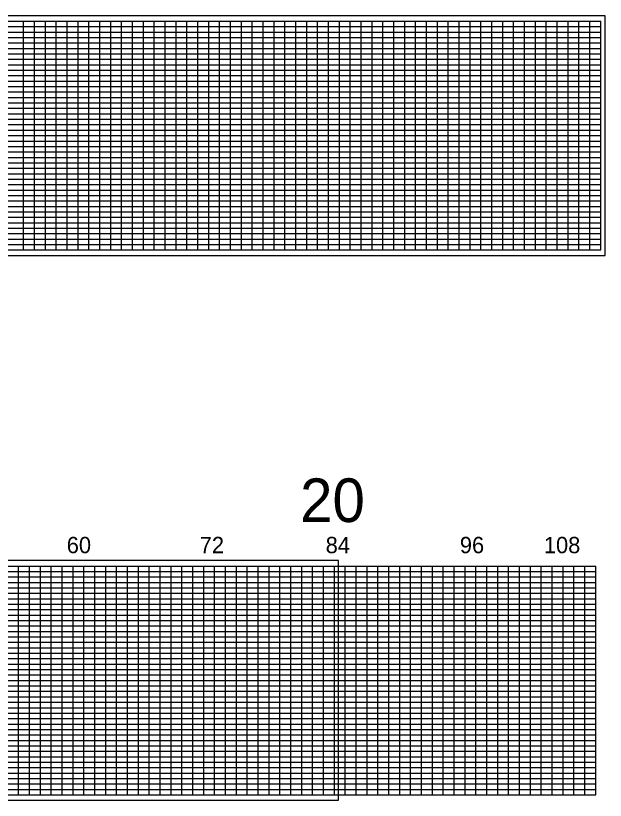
# Model space of a CAD drawing. Extents: x 1914168 to 1925341, y 720939 to 777401.
# Drawn here: x 1922518 to 1925226, y 735939 to 739539 of the extents above; entities that cross this region are included whole.
import ezdxf

# ---------------------------------------------------------------- set-up
doc = ezdxf.new("R2010")
doc.units = 0
for name, color, linetype in [('RD_PD_ALT1_CL', 7, 'Continuous'), ('RD_PD_WallFill', 7, 'Continuous'), ('RD_SHT_IplotShp', 7, 'Continuous')]:
    doc.layers.add(name, color=color, linetype=linetype)

msp = doc.modelspace()

# ---------------------------------------------------------------- linework, layer by layer
at = {"layer": 'RD_PD_WallFill'}
for p, q in [((1919854.9, 739514.2), (1925204.9, 739514.2)), ((1922554.9, 738464.2), (1922554.9, 739514.2)), ((1922554.9, 738464.2), (1922554.9, 739514.2)), ((1922604.9, 738464.2), (1922604.9, 739514.2)), ((1922604.9, 738464.2), (1922604.9, 739514.2)), ((1922654.9, 738464.2), (1922654.9, 739514.2)), ((1922654.9, 738464.2), (1922654.9, 739514.2)), ((1922704.9, 738464.2), (1922704.9, 739514.2)), ((1922704.9, 738464.2), (1922704.9, 739514.2)), ((1922754.9, 738464.2), (1922754.9, 739514.2)), ((1922754.9, 738464.2), (1922754.9, 739514.2)), ((1922804.9, 738464.2), (1922804.9, 739514.2)), ((1922804.9, 738464.2), (1922804.9, 739514.2)), ((1922854.9, 738464.2), (1922854.9, 739514.2)), ((1922854.9, 738464.2), (1922854.9, 739514.2)), ((1922904.9, 738464.2), (1922904.9, 739514.2)), ((1922904.9, 738464.2), (1922904.9, 739514.2)), ((1922954.9, 738464.2), (1922954.9, 739514.2)), ((1922954.9, 738464.2), (1922954.9, 739514.2)), ((1923004.9, 738464.2), (1923004.9, 739514.2)), ((1923004.9, 738464.2), (1923004.9, 739514.2)), ((1923054.9, 738464.2), (1923054.9, 739514.2)), ((1923054.9, 738464.2), (1923054.9, 739514.2)), ((1923104.9, 738464.2), (1923104.9, 739514.2)), ((1923104.9, 738464.2), (1923104.9, 739514.2)), ((1923154.9, 738464.2), (1923154.9, 739514.2)), ((1923154.9, 738464.2), (1923154.9, 739514.2)), ((1923204.9, 738464.2), (1923204.9, 739514.2)), ((1923204.9, 738464.2), (1923204.9, 739514.2)), ((1923254.9, 738464.2), (1923254.9, 739514.2)), ((1923254.9, 738464.2), (1923254.9, 739514.2)), ((1923304.9, 738464.2), (1923304.9, 739514.2)), ((1923304.9, 738464.2), (1923304.9, 739514.2)), ((1923354.9, 738464.2), (1923354.9, 739514.2)), ((1923354.9, 738464.2), (1923354.9, 739514.2)), ((1923404.9, 738464.2), (1923404.9, 739514.2)), ((1923404.9, 738464.2), (1923404.9, 739514.2)), ((1923454.9, 738464.2), (1923454.9, 739514.2)), ((1923454.9, 738464.2), (1923454.9, 739514.2)), ((1923504.9, 738464.2), (1923504.9, 739514.2)), ((1923504.9, 738464.2), (1923504.9, 739514.2)), ((1923554.9, 738464.2), (1923554.9, 739514.2)), ((1923554.9, 738464.2), (1923554.9, 739514.2)), ((1923604.9, 738464.2), (1923604.9, 739514.2)), ((1923604.9, 738464.2), (1923604.9, 739514.2)), ((1923654.9, 738464.2), (1923654.9, 739514.2)), ((1923654.9, 738464.2), (1923654.9, 739514.2)), ((1923704.9, 738464.2), (1923704.9, 739514.2)), ((1923704.9, 738464.2), (1923704.9, 739514.2)), ((1923754.9, 738464.2), (1923754.9, 739514.2)), ((1923754.9, 738464.2), (1923754.9, 739514.2)), ((1923804.9, 738464.2), (1923804.9, 739514.2)), ((1923804.9, 738464.2), (1923804.9, 739514.2)), ((1923854.9, 738464.2), (1923854.9, 739514.2)), ((1923854.9, 738464.2), (1923854.9, 739514.2)), ((1923904.9, 738464.2), (1923904.9, 739514.2)), ((1923904.9, 738464.2), (1923904.9, 739514.2)), ((1923954.9, 738464.2), (1923954.9, 739514.2)), ((1923954.9, 738464.2), (1923954.9, 739514.2)), ((1924004.9, 738464.2), (1924004.9, 739514.2)), ((1924004.9, 738464.2), (1924004.9, 739514.2)), ((1924054.9, 738464.2), (1924054.9, 739514.2)), ((1924054.9, 738464.2), (1924054.9, 739514.2)), ((1924104.9, 738464.2), (1924104.9, 739514.2)), ((1924104.9, 738464.2), (1924104.9, 739514.2)), ((1924154.9, 738464.2), (1924154.9, 739514.2)), ((1924154.9, 738464.2), (1924154.9, 739514.2)), ((1924204.9, 738464.2), (1924204.9, 739514.2)), ((1924204.9, 738464.2), (1924204.9, 739514.2)), ((1924254.9, 738464.2), (1924254.9, 739514.2)), ((1924254.9, 738464.2), (1924254.9, 739514.2)), ((1924304.9, 738464.2), (1924304.9, 739514.2)), ((1924304.9, 738464.2), (1924304.9, 739514.2)), ((1924354.9, 738464.2), (1924354.9, 739514.2)), ((1924354.9, 738464.2), (1924354.9, 739514.2)), ((1924404.9, 738464.2), (1924404.9, 739514.2)), ((1924404.9, 738464.2), (1924404.9, 739514.2)), ((1924454.9, 738464.2), (1924454.9, 739514.2)), ((1924454.9, 738464.2), (1924454.9, 739514.2)), ((1924504.9, 738464.2), (1924504.9, 739514.2)), ((1924504.9, 738464.2), (1924504.9, 739514.2)), ((1924554.9, 738464.2), (1924554.9, 739514.2)), ((1924554.9, 738464.2), (1924554.9, 739514.2)), ((1924604.9, 738464.2), (1924604.9, 739514.2)), ((1924604.9, 738464.2), (1924604.9, 739514.2)), ((1924654.9, 738464.2), (1924654.9, 739514.2)), ((1924654.9, 738464.2), (1924654.9, 739514.2)), ((1924704.9, 738464.2), (1924704.9, 739514.2)), ((1924704.9, 738464.2), (1924704.9, 739514.2)), ((1924754.9, 738464.2), (1924754.9, 739514.2)), ((1924754.9, 738464.2), (1924754.9, 739514.2)), ((1924804.9, 738464.2), (1924804.9, 739514.2)), ((1924804.9, 738464.2), (1924804.9, 739514.2)), ((1924854.9, 738464.2), (1924854.9, 739514.2)), ((1924854.9, 738464.2), (1924854.9, 739514.2)), ((1924904.9, 738464.2), (1924904.9, 739514.2)), ((1924904.9, 738464.2), (1924904.9, 739514.2)), ((1924954.9, 738464.2), (1924954.9, 739514.2)), ((1924954.9, 738464.2), (1924954.9, 739514.2)), ((1925005, 738464.2), (1925005, 739514.2)), ((1925005, 738464.2), (1925005, 739514.2)), ((1925054.9, 738464.2), (1925055, 739514.2)), ((1925054.9, 738464.2), (1925055, 739514.2)), ((1925104.9, 738464.2), (1925104.9, 739514.2)), ((1925104.9, 738464.2), (1925104.9, 739514.2)), ((1925154.9, 738464.2), (1925154.9, 739514.2)), ((1925154.9, 738464.2), (1925154.9, 739514.2)), ((1925205, 738464.2), (1925205, 739514.2)), ((1925205, 738464.2), (1925205, 739514.2)), ((1920304.9, 739489.2), (1925204.9, 739489.2)), ((1920304.9, 739489.2), (1925204.9, 739489.2)), ((1920304.9, 739464.2), (1925204.9, 739464.2)), ((1920304.9, 739439.2), (1925204.9, 739439.2)), ((1920304.9, 739414.2), (1925204.9, 739414.2)), ((1920304.9, 739389.2), (1925204.9, 739389.2)), ((1919854.9, 739364.2), (1925204.9, 739364.2)), ((1919854.9, 739339.2), (1925204.9, 739339.2)), ((1919854.9, 739314.2), (1925204.9, 739314.2)), ((1919854.9, 739289.2), (1925204.9, 739289.2)), ((1919854.9, 739264.2), (1925204.9, 739264.2)), ((1919854.9, 739239.2), (1925204.9, 739239.2)), ((1919854.9, 739214.2), (1925204.9, 739214.2)), ((1919854.9, 739189.2), (1925204.9, 739189.2)), ((1919854.9, 739164.2), (1925204.9, 739164.2)), ((1919854.9, 739139.2), (1925204.9, 739139.2)), ((1919854.9, 739114.2), (1925204.9, 739114.2)), ((1919854.9, 739089.2), (1925204.9, 739089.2)), ((1919854.9, 739064.2), (1925204.9, 739064.2)), ((1919854.9, 739039.2), (1925204.9, 739039.2)), ((1919854.9, 739014.2), (1925204.9, 739014.2)), ((1919854.9, 738989.2), (1925204.9, 738989.2)), ((1919854.9, 738964.2), (1925204.9, 738964.2)), ((1919854.9, 738939.2), (1925204.9, 738939.2)), ((1919854.9, 738914.2), (1925204.9, 738914.2)), ((1919854.9, 738889.2), (1925204.9, 738889.2)), ((1919854.9, 738864.2), (1925204.9, 738864.2)), ((1919854.9, 738839.2), (1925204.9, 738839.2)), ((1919854.9, 738814.2), (1925204.9, 738814.2)), ((1919854.9, 738789.2), (1925204.9, 738789.2)), ((1919854.9, 738764.2), (1925204.9, 738764.2)), ((1919854.9, 738739.2), (1925204.9, 738739.2)), ((1919854.9, 738714.2), (1925204.9, 738714.2)), ((1919854.9, 738689.2), (1925204.9, 738689.2)), ((1919854.9, 738664.2), (1925204.9, 738664.2)), ((1919854.9, 738639.2), (1925204.9, 738639.2)), ((1919854.9, 738614.2), (1925204.9, 738614.2)), ((1919854.9, 738589.2), (1925204.9, 738589.2)), ((1919854.9, 738564.2), (1925204.9, 738564.2)), ((1919854.9, 738539.2), (1925204.9, 738539.2)), ((1919854.9, 738514.2), (1925204.9, 738514.2)), ((1919854.9, 738489.2), (1925204.9, 738489.2)), ((1919854.9, 738464.2), (1925204.9, 738464.2)), ((1919854.9, 738464.2), (1925204.9, 738464.2)), ((1919831.8, 737014.2), (1925181.8, 737014.2)), ((1922531.8, 735964.2), (1922531.8, 737014.2)), ((1922531.8, 735964.2), (1922531.8, 737014.2)), ((1922581.8, 735964.2), (1922581.8, 737014.2)), ((1922581.8, 735964.2), (1922581.8, 737014.2)), ((1922631.8, 735964.2), (1922631.8, 737014.2)), ((1922631.8, 735964.2), (1922631.8, 737014.2)), ((1922681.8, 735964.2), (1922681.8, 737014.2)), ((1922681.8, 735964.2), (1922681.8, 737014.2)), ((1922731.8, 735964.2), (1922731.8, 737014.2)), ((1922731.8, 735964.2), (1922731.8, 737014.2)), ((1922781.8, 735964.2), (1922781.8, 737014.2)), ((1922781.8, 735964.2), (1922781.8, 737014.2)), ((1922831.8, 735964.2), (1922831.8, 737014.2)), ((1922831.8, 735964.2), (1922831.8, 737014.2)), ((1922881.8, 735964.2), (1922881.8, 737014.2)), ((1922881.8, 735964.2), (1922881.8, 737014.2)), ((1922931.8, 735964.2), (1922931.8, 737014.2)), ((1922931.8, 735964.2), (1922931.8, 737014.2)), ((1922981.8, 735964.2), (1922981.8, 737014.2)), ((1922981.8, 735964.2), (1922981.8, 737014.2)), ((1923031.8, 735964.2), (1923031.8, 737014.2)), ((1923031.8, 735964.2), (1923031.8, 737014.2)), ((1923081.8, 735964.2), (1923081.8, 737014.2)), ((1923081.8, 735964.2), (1923081.8, 737014.2)), ((1923131.8, 735964.2), (1923131.8, 737014.2)), ((1923131.8, 735964.2), (1923131.8, 737014.2)), ((1923181.8, 735964.2), (1923181.8, 737014.2)), ((1923181.8, 735964.2), (1923181.8, 737014.2)), ((1923231.8, 735964.2), (1923231.8, 737014.2)), ((1923231.8, 735964.2), (1923231.8, 737014.2)), ((1923281.8, 735964.2), (1923281.8, 737014.2)), ((1923281.8, 735964.2), (1923281.8, 737014.2)), ((1923331.8, 735964.2), (1923331.8, 737014.2)), ((1923331.8, 735964.2), (1923331.8, 737014.2)), ((1923381.8, 735964.2), (1923381.8, 737014.2)), ((1923381.8, 735964.2), (1923381.8, 737014.2)), ((1923431.8, 735964.2), (1923431.8, 737014.2)), ((1923431.8, 735964.2), (1923431.8, 737014.2)), ((1923481.8, 735964.2), (1923481.8, 737014.2)), ((1923481.8, 735964.2), (1923481.8, 737014.2)), ((1923531.8, 735964.2), (1923531.8, 737014.2)), ((1923531.8, 735964.2), (1923531.8, 737014.2)), ((1923581.8, 735964.2), (1923581.8, 737014.2)), ((1923581.8, 735964.2), (1923581.8, 737014.2)), ((1923631.8, 735964.2), (1923631.8, 737014.2)), ((1923631.8, 735964.2), (1923631.8, 737014.2)), ((1923681.8, 735964.2), (1923681.8, 737014.2)), ((1923681.8, 735964.2), (1923681.8, 737014.2)), ((1923731.8, 735964.2), (1923731.8, 737014.2)), ((1923731.8, 735964.2), (1923731.8, 737014.2)), ((1923781.8, 735964.2), (1923781.8, 737014.2)), ((1923781.8, 735964.2), (1923781.8, 737014.2)), ((1923831.8, 735964.2), (1923831.8, 737014.2)), ((1923831.8, 735964.2), (1923831.8, 737014.2)), ((1923881.8, 735964.2), (1923881.8, 737014.2)), ((1923881.8, 735964.2), (1923881.8, 737014.2)), ((1923931.8, 735964.2), (1923931.8, 737014.2)), ((1923931.8, 735964.2), (1923931.8, 737014.2)), ((1923981.8, 735964.2), (1923981.8, 737014.2)), ((1923981.8, 735964.2), (1923981.8, 737014.2)), ((1924031.8, 735964.2), (1924031.8, 737014.2)), ((1924031.8, 735964.2), (1924031.8, 737014.2)), ((1924081.8, 735964.2), (1924081.8, 737014.2)), ((1924081.8, 735964.2), (1924081.8, 737014.2)), ((1924131.8, 735964.2), (1924131.8, 737014.2)), ((1924131.8, 735964.2), (1924131.8, 737014.2)), ((1924181.8, 735964.2), (1924181.8, 737014.2)), ((1924181.8, 735964.2), (1924181.8, 737014.2)), ((1924231.8, 735964.2), (1924231.8, 737014.2)), ((1924231.8, 735964.2), (1924231.8, 737014.2)), ((1924281.8, 735964.2), (1924281.8, 737014.2)), ((1924281.8, 735964.2), (1924281.8, 737014.2)), ((1924331.8, 735964.2), (1924331.8, 737014.2)), ((1924331.8, 735964.2), (1924331.8, 737014.2)), ((1924381.8, 735964.2), (1924381.8, 737014.2)), ((1924381.8, 735964.2), (1924381.8, 737014.2)), ((1924431.8, 735964.2), (1924431.8, 737014.2)), ((1924431.8, 735964.2), (1924431.8, 737014.2)), ((1924481.8, 735964.2), (1924481.8, 737014.2)), ((1924481.8, 735964.2), (1924481.8, 737014.2)), ((1924531.8, 735964.2), (1924531.8, 737014.2)), ((1924531.8, 735964.2), (1924531.8, 737014.2)), ((1924581.8, 735964.2), (1924581.8, 737014.2)), ((1924581.8, 735964.2), (1924581.8, 737014.2)), ((1924631.8, 735964.2), (1924631.8, 737014.2)), ((1924631.8, 735964.2), (1924631.8, 737014.2)), ((1924681.8, 735964.2), (1924681.8, 737014.2)), ((1924681.8, 735964.2), (1924681.8, 737014.2)), ((1924731.8, 735964.2), (1924731.8, 737014.2)), ((1924731.8, 735964.2), (1924731.8, 737014.2)), ((1924781.8, 735964.2), (1924781.8, 737014.2)), ((1924781.8, 735964.2), (1924781.8, 737014.2)), ((1924831.8, 735964.2), (1924831.8, 737014.2)), ((1924831.8, 735964.2), (1924831.8, 737014.2)), ((1924881.8, 735964.2), (1924881.8, 737014.2)), ((1924881.8, 735964.2), (1924881.8, 737014.2)), ((1924931.8, 735964.2), (1924931.8, 737014.2)), ((1924931.8, 735964.2), (1924931.8, 737014.2)), ((1924981.8, 735964.2), (1924981.8, 737014.2)), ((1924981.8, 735964.2), (1924981.8, 737014.2)), ((1925031.8, 735964.2), (1925031.8, 737014.2)), ((1925031.8, 735964.2), (1925031.8, 737014.2)), ((1925081.8, 735964.2), (1925081.8, 737014.2)), ((1925081.8, 735964.2), (1925081.8, 737014.2)), ((1925131.8, 735964.2), (1925131.8, 737014.2)), ((1925131.8, 735964.2), (1925131.8, 737014.2)), ((1925181.8, 735964.2), (1925181.8, 737014.2)), ((1925181.8, 735964.2), (1925181.8, 737014.2)), ((1920281.8, 736989.2), (1925181.8, 736989.2)), ((1920281.8, 736989.2), (1925181.8, 736989.2)), ((1920281.8, 736964.2), (1925181.8, 736964.2)), ((1920281.8, 736939.2), (1925181.8, 736939.2)), ((1920281.8, 736914.2), (1925181.8, 736914.2)), ((1920281.8, 736889.2), (1925181.8, 736889.2)), ((1919831.8, 736864.2), (1925181.8, 736864.2)), ((1919831.8, 736839.2), (1925181.8, 736839.2)), ((1919831.8, 736814.2), (1925181.8, 736814.2)), ((1919831.8, 736789.2), (1925181.8, 736789.2)), ((1919831.8, 736764.2), (1925181.8, 736764.2)), ((1919831.8, 736739.2), (1925181.8, 736739.2)), ((1919831.8, 736714.2), (1925181.8, 736714.2)), ((1919831.8, 736689.2), (1925181.8, 736689.2)), ((1919831.8, 736664.2), (1925181.8, 736664.2)), ((1919831.8, 736639.2), (1925181.8, 736639.2)), ((1919831.8, 736614.2), (1925181.8, 736614.2)), ((1919831.8, 736589.2), (1925181.8, 736589.2)), ((1919831.8, 736564.2), (1925181.8, 736564.2)), ((1919831.8, 736539.2), (1925181.8, 736539.2)), ((1919831.8, 736514.2), (1925181.8, 736514.2)), ((1919831.8, 736489.2), (1925181.8, 736489.2)), ((1919831.8, 736464.2), (1925181.8, 736464.2)), ((1919831.8, 736439.2), (1925181.8, 736439.2)), ((1919831.8, 736414.2), (1925181.8, 736414.2)), ((1919831.8, 736389.2), (1925181.8, 736389.2)), ((1919831.8, 736364.2), (1925181.8, 736364.2)), ((1919831.8, 736339.2), (1925181.8, 736339.2)), ((1919831.8, 736314.2), (1925181.8, 736314.2)), ((1919831.8, 736289.2), (1925181.8, 736289.2)), ((1919831.8, 736264.2), (1925181.8, 736264.2)), ((1919831.8, 736239.2), (1925181.8, 736239.2)), ((1919831.8, 736214.2), (1925181.8, 736214.2)), ((1919831.8, 736189.2), (1925181.8, 736189.2)), ((1919831.8, 736164.2), (1925181.8, 736164.2)), ((1919831.8, 736139.2), (1925181.8, 736139.2)), ((1919831.8, 736114.2), (1925181.8, 736114.2)), ((1919831.8, 736089.2), (1925181.8, 736089.2)), ((1919831.8, 736064.2), (1925181.8, 736064.2)), ((1919831.8, 736039.2), (1925181.8, 736039.2)), ((1919831.8, 736014.2), (1925181.8, 736014.2)), ((1919831.8, 735989.2), (1925181.8, 735989.2)), ((1919831.8, 735964.2), (1925181.8, 735964.2)), ((1919831.8, 735964.2), (1925181.8, 735964.2))]:
    msp.add_line(p, q, dxfattribs=at)
at = {"layer": 'RD_SHT_IplotShp'}
for points in [[(1919825.9, 738439.1), (1925225.9, 738439.1), (1925225.9, 739539.1), (1919825.9, 739539.1)], [(1919800.4, 735939.1), (1924000.4, 735939.1), (1924000.4, 737039.1), (1919800.4, 737039.1)]]:
    msp.add_lwpolyline(points, close=True, dxfattribs=at)

# ---------------------------------------------------------------- texts
at = {"layer": 'RD_PD_ALT1_CL'}
msp.add_text('20', height=200, dxfattribs=at).set_placement((1923824.3, 737216))
at = {"layer": 'RD_PD_WallFill'}
for s, p in [('60', (1922752.9, 737072.9)), ('60', (1922752.9, 737072.9)), ('72', (1923363.6, 737072.9)), ('72', (1923363.6, 737072.9)), ('84', (1923941.8, 737072.9)), ('84', (1923941.8, 737072.9)), ('96', (1924557.9, 737072.9)), ('96', (1924557.9, 737072.9)), ('108', (1924943.7, 737072.9))]:
    msp.add_text(s, height=75, dxfattribs=at).set_placement(p)

doc.saveas('drawing.dxf')
